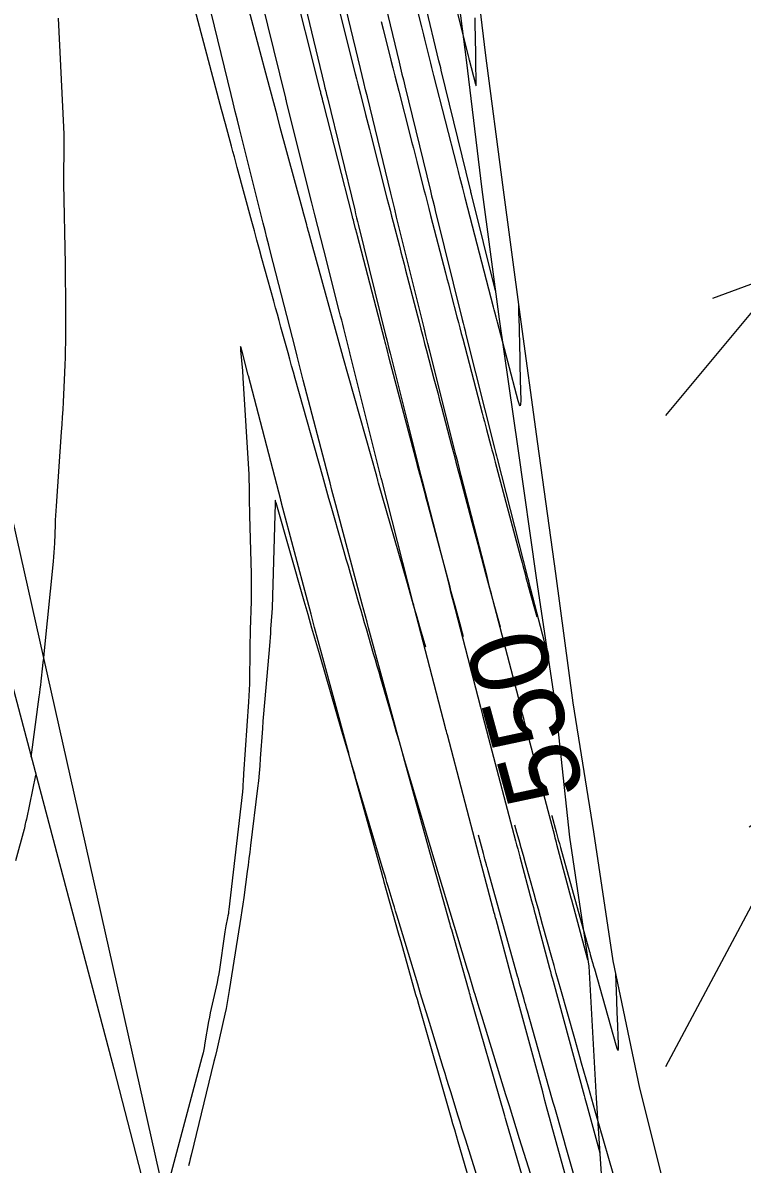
# Model space of a CAD drawing. Extents: x 954385 to 988206, y 1868364 to 1924553.
# Drawn here: x 957857.8 to 957913, y 1919611.4 to 1919699.1 of the extents above; entities that cross this region are included whole.
import ezdxf

# ---------------------------------------------------------------- set-up
doc = ezdxf.new("R2010")
doc.units = 0
for name, color, linetype in [('1', 7, 'Continuous'), ('Default', 7, 'Continuous'), ('Ex_Contour Labels', 7, 'Continuous'), ('Ex_Major Contours', 7, 'Continuous'), ('Ex_Minor Contours', 7, 'Continuous'), ('Perimeter', 7, 'Continuous'), ('Slopes', 7, 'Continuous')]:
    doc.layers.add(name, color=color, linetype=linetype)

msp = doc.modelspace()

# ---------------------------------------------------------------- linework, layer by layer
msp.add_lwpolyline([(957857.224, 1919634.741), (957857.897, 1919637.166), (957857.914, 1919637.23), (957857.93, 1919637.294), (957857.945, 1919637.359), (957857.96, 1919637.424), (957858.037, 1919637.793), (957858.04, 1919637.803), (957858.042, 1919637.814), (957858.045, 1919637.824), (957858.047, 1919637.834), (957858.059, 1919637.875), (957858.061, 1919637.886), (957858.064, 1919637.896), (957858.067, 1919637.906), (957858.069, 1919637.917), (957858.774, 1919641.289)])
at = {"layer": '1'}
for points in [[(957890.519, 1919706.211), (957891.799, 1919696.25), (957893.016, 1919686.274), (957894.336, 1919676.322), (957895.78, 1919666.397), (957897.186, 1919656.464), (957898.672, 1919646.548), (957899.744, 1919636.541), (957900.425, 1919631.907), (957901.213, 1919626.621), (957901.79, 1919616.502), (957902.451, 1919606.402), (957903.226, 1919596.327), (957904.28, 1919586.315), (957905.605, 1919576.364), (957907.064, 1919566.442), (957908.777, 1919559.571)], [(957894.046, 1919678.504), (957892.213, 1919685.917), (957892.192, 1919686.001), (957892.171, 1919686.085), (957892.151, 1919686.169), (957892.13, 1919686.253), (957889.894, 1919695.436), (957889.849, 1919695.619), (957889.805, 1919695.802), (957889.761, 1919695.985), (957889.717, 1919696.169), (957887.599, 1919705.006)], [(957878.8, 1919703.107), (957880.899, 1919694.347), (957880.961, 1919694.089), (957881.023, 1919693.832), (957881.086, 1919693.574), (957881.148, 1919693.316), (957883.245, 1919684.709), (957883.317, 1919684.411), (957883.39, 1919684.114), (957883.463, 1919683.817), (957883.536, 1919683.52), (957885.622, 1919675.092), (957885.707, 1919674.748), (957885.792, 1919674.404), (957885.878, 1919674.061), (957885.964, 1919673.718), (957888.027, 1919665.509), (957888.129, 1919665.106), (957888.231, 1919664.703), (957888.333, 1919664.3), (957888.436, 1919663.897), (957890.462, 1919655.959), (957890.583, 1919655.484), (957890.705, 1919655.009), (957890.827, 1919654.535), (957890.95, 1919654.061), (957892.906, 1919646.512), (957893.06, 1919645.918), (957893.215, 1919645.324), (957893.37, 1919644.731), (957893.526, 1919644.137), (957895.597, 1919636.265), (957895.679, 1919635.956), (957895.76, 1919635.647), (957895.842, 1919635.337), (957895.925, 1919635.028), (957896.825, 1919631.641), (957896.893, 1919631.385), (957896.962, 1919631.13), (957897.03, 1919630.875), (957897.098, 1919630.619), (957898.205, 1919626.488), (957898.274, 1919626.233), (957898.342, 1919625.977), (957898.411, 1919625.722), (957898.48, 1919625.467), (957900.859, 1919616.686), (957900.91, 1919616.501), (957900.96, 1919616.316), (957901.011, 1919616.131), (957901.061, 1919615.946), (957902.065, 1919612.295)], [(957901.139, 1919627.121), (957899.91, 1919631.708), (957899.889, 1919631.787), (957899.867, 1919631.866), (957898.774, 1919635.976), (957898.731, 1919636.14), (957898.688, 1919636.303), (957898.644, 1919636.467), (957898.601, 1919636.63), (957896.321, 1919645.299), (957896.231, 1919645.64), (957896.142, 1919645.981), (957896.053, 1919646.322), (957895.964, 1919646.664), (957893.861, 1919654.78), (957893.746, 1919655.223), (957893.632, 1919655.666), (957893.518, 1919656.11), (957893.405, 1919656.553), (957891.429, 1919664.296), (957891.293, 1919664.828), (957891.158, 1919665.36), (957891.024, 1919665.892), (957890.89, 1919666.424), (957889.022, 1919673.857), (957888.87, 1919674.459), (957888.72, 1919675.061), (957888.57, 1919675.664), (957888.421, 1919676.266), (957886.619, 1919683.549), (957886.468, 1919684.16), (957886.318, 1919684.771), (957886.168, 1919685.382), (957886.019, 1919685.994), (957884.217, 1919693.391), (957884.084, 1919693.94), (957883.951, 1919694.489), (957883.819, 1919695.038), (957883.687, 1919695.587), (957881.857, 1919703.225)], [(957884.792, 1919703.846), (957886.661, 1919696.05), (957886.769, 1919695.598), (957886.878, 1919695.145), (957886.988, 1919694.693), (957887.097, 1919694.241), (957889.061, 1919686.178), (957889.153, 1919685.803), (957889.244, 1919685.428), (957889.337, 1919685.053), (957889.429, 1919684.678), (957891.503, 1919676.295), (957891.575, 1919676.007), (957891.647, 1919675.718), (957891.719, 1919675.43), (957891.791, 1919675.141), (957893.986, 1919666.407), (957894.035, 1919666.212), (957894.085, 1919666.017), (957894.134, 1919665.821), (957894.184, 1919665.626), (957896.518, 1919656.48), (957896.539, 1919656.401), (957896.559, 1919656.323), (957896.579, 1919656.245), (957896.599, 1919656.167), (957898.096, 1919650.39)], [(957900.382, 1919607.112), (957898.392, 1919614.352), (957898.212, 1919615.006), (957898.034, 1919615.659), (957897.856, 1919616.313), (957897.678, 1919616.967), (957895.615, 1919624.581), (957895.515, 1919624.951), (957895.415, 1919625.32), (957895.316, 1919625.69), (957895.217, 1919626.06), (957894.103, 1919630.216), (957894.069, 1919630.345), (957894.034, 1919630.473), (957894, 1919630.601), (957893.966, 1919630.73), (957892.882, 1919634.803), (957892.858, 1919634.896), (957892.833, 1919634.99), (957892.808, 1919635.083), (957892.784, 1919635.176), (957890.361, 1919644.386), (957890.324, 1919644.526), (957890.287, 1919644.667), (957890.251, 1919644.808), (957890.214, 1919644.948), (957887.818, 1919654.194), (957887.797, 1919654.273), (957887.777, 1919654.352), (957887.757, 1919654.432), (957887.736, 1919654.511), (957885.322, 1919663.97), (957885.312, 1919664.008), (957885.303, 1919664.046), (957885.293, 1919664.084), (957885.284, 1919664.122), (957882.868, 1919673.735), (957882.861, 1919673.76), (957882.402, 1919675.615), (957882.325, 1919675.927), (957882.247, 1919676.238), (957882.169, 1919676.549), (957882.09, 1919676.859), (957880.869, 1919681.643), (957880.64, 1919682.544), (957880.412, 1919683.446), (957880.185, 1919684.347), (957879.959, 1919685.249), (957878.018, 1919693.015), (957878.001, 1919693.082), (957877.984, 1919693.15), (957877.968, 1919693.217), (957877.951, 1919693.284), (957875.656, 1919702.664)], [(957897.591, 1919605.464), (957894.933, 1919614.566), (957894.879, 1919614.753), (957894.825, 1919614.939), (957894.771, 1919615.126), (957894.717, 1919615.313), (957892.147, 1919624.279), (957892.106, 1919624.424), (957892.064, 1919624.568), (957892.023, 1919624.713), (957891.982, 1919624.858), (957890.695, 1919629.411), (957890.654, 1919629.558), (957890.612, 1919629.705), (957890.571, 1919629.852), (957890.53, 1919629.999), (957889.556, 1919633.479), (957889.454, 1919633.844), (957889.352, 1919634.208), (957889.251, 1919634.573), (957889.15, 1919634.938), (957887.1, 1919642.361), (957886.894, 1919643.11), (957886.689, 1919643.859), (957886.484, 1919644.609), (957886.28, 1919645.359), (957884.318, 1919652.605), (957884.194, 1919653.063), (957884.071, 1919653.521), (957883.948, 1919653.979), (957883.826, 1919654.437), (957881.801, 1919662.061), (957881.651, 1919662.627), (957881.502, 1919663.193), (957881.354, 1919663.759), (957881.206, 1919664.326), (957879.301, 1919671.643), (957879.141, 1919672.259), (957878.981, 1919672.876), (957878.823, 1919673.493), (957878.665, 1919674.11), (957876.79, 1919681.457), (957876.649, 1919682.013), (957876.508, 1919682.57), (957876.368, 1919683.126), (957876.228, 1919683.683), (957874.409, 1919690.961), (957874.246, 1919691.618), (957874.083, 1919692.274), (957873.921, 1919692.931), (957873.76, 1919693.588), (957871.959, 1919700.947)], [(957893.365, 1919605.696), (957891.193, 1919613.133), (957891.058, 1919613.598), (957890.923, 1919614.064), (957890.788, 1919614.529), (957890.655, 1919614.995), (957888.372, 1919622.957), (957888.267, 1919623.325), (957888.162, 1919623.693), (957888.057, 1919624.06), (957887.953, 1919624.428), (957886.802, 1919628.501), (957886.756, 1919628.665), (957886.71, 1919628.829), (957886.663, 1919628.994), (957886.617, 1919629.158), (957885.519, 1919633.082), (957885.484, 1919633.207), (957885.449, 1919633.333), (957885.414, 1919633.458), (957885.379, 1919633.584), (957882.882, 1919642.628), (957882.833, 1919642.806), (957882.784, 1919642.983), (957882.736, 1919643.161), (957882.688, 1919643.338), (957880.725, 1919650.584), (957880.447, 1919651.615), (957880.169, 1919652.645), (957879.894, 1919653.676), (957879.619, 1919654.707), (957877.633, 1919662.185), (957877.615, 1919662.251), (957877.598, 1919662.317), (957877.581, 1919662.383), (957877.564, 1919662.449), (957875.083, 1919671.976), (957875.074, 1919672.012), (957875.071, 1919672.023), (957874.58, 1919673.948), (957874.523, 1919674.149), (957874.489, 1919674.214), (957874.479, 1919674.142), (957874.492, 1919673.933), (957874.633, 1919672.366), (957874.637, 1919672.32), (957874.64, 1919672.274), (957874.643, 1919672.228), (957874.645, 1919672.182), (957874.653, 1919671.998), (957874.655, 1919671.952), (957874.657, 1919671.905), (957874.659, 1919671.859), (957874.662, 1919671.813), (957875.107, 1919664.398), (957875.121, 1919664.135), (957875.131, 1919663.872), (957875.138, 1919663.609), (957875.142, 1919663.347), (957875.151, 1919662.295), (957875.154, 1919662.032), (957875.158, 1919661.769), (957875.163, 1919661.506), (957875.169, 1919661.243), (957875.291, 1919656.772), (957875.301, 1919656.248), (957875.305, 1919655.724), (957875.3, 1919655.2), (957875.289, 1919654.675), (957875.225, 1919652.451), (957875.213, 1919651.99), (957875.203, 1919651.53), (957875.195, 1919651.069), (957875.19, 1919650.608), (957875.174, 1919648.765), (957875.166, 1919648.304), (957875.152, 1919647.844), (957875.13, 1919647.384), (957875.101, 1919646.924), (957874.717, 1919641.399), (957874.709, 1919641.284), (957874.702, 1919641.169), (957874.696, 1919641.054), (957874.69, 1919640.939), (957874.667, 1919640.478), (957874.661, 1919640.363), (957874.652, 1919640.248), (957874.642, 1919640.133), (957874.63, 1919640.019), (957873.591, 1919630.98), (957873.571, 1919630.822), (957873.547, 1919630.664), (957873.52, 1919630.508), (957873.49, 1919630.351), (957873.362, 1919629.727), (957873.331, 1919629.571), (957873.303, 1919629.414), (957873.276, 1919629.257), (957873.252, 1919629.1), (957872.856, 1919626.369), (957872.804, 1919626.034), (957872.745, 1919625.701), (957872.679, 1919625.369), (957872.606, 1919625.039), (957872.301, 1919623.719), (957872.227, 1919623.388), (957872.158, 1919623.057), (957872.093, 1919622.724), (957872.034, 1919622.391), (957871.751, 1919620.75), (957871.68, 1919620.366), (957871.601, 1919619.984), (957871.513, 1919619.604), (957871.417, 1919619.226), (957868.747, 1919609.237)]]:
    msp.add_lwpolyline(points, dxfattribs=at)
at = {"layer": 'Default'}
msp.add_line((958200.602, 1918129.717), (957843.865, 1919719.405), dxfattribs=at)
at = {"layer": 'Ex_Major Contours'}
for points in [[(957881.873, 1919700.777), (957883.286, 1919695.163), (957883.384, 1919694.773), (957883.483, 1919694.384), (957883.582, 1919693.994), (957883.681, 1919693.604), (957884.079, 1919692.046), (957884.179, 1919691.656), (957884.278, 1919691.266), (957884.378, 1919690.877), (957884.478, 1919690.487), (957885.725, 1919685.611), (957885.843, 1919685.151), (957885.961, 1919684.691), (957886.08, 1919684.23), (957886.199, 1919683.77), (957886.676, 1919681.93), (957886.795, 1919681.47), (957886.915, 1919681.01), (957887.034, 1919680.549), (957887.153, 1919680.089), (957888.19, 1919676.095), (957888.331, 1919675.551), (957888.473, 1919675.006), (957888.616, 1919674.462), (957888.759, 1919673.918), (957889.332, 1919671.742), (957889.475, 1919671.197), (957889.618, 1919670.653), (957889.762, 1919670.109), (957889.905, 1919669.565), (957890.681, 1919666.617), (957890.851, 1919665.973), (957891.021, 1919665.329), (957891.192, 1919664.685), (957891.364, 1919664.041), (957892.094, 1919661.309), (957892.245, 1919660.744), (957892.396, 1919660.179), (957892.547, 1919659.614), (957892.698, 1919659.049), (957893.301, 1919656.79), (957893.453, 1919656.225), (957893.604, 1919655.66), (957893.757, 1919655.096), (957893.909, 1919654.531), (957894.409, 1919652.689)], [(957898.361, 1919638.219), (957898.374, 1919638.174), (957898.708, 1919636.955), (957898.792, 1919636.65), (957898.877, 1919636.346), (957898.961, 1919636.041), (957899.046, 1919635.737), (957901.18, 1919628.087), (957901.219, 1919627.949), (957901.257, 1919627.81), (957901.296, 1919627.671), (957901.335, 1919627.533), (957901.489, 1919626.978), (957901.528, 1919626.839), (957901.567, 1919626.701), (957901.606, 1919626.562), (957901.645, 1919626.424), (957903.297, 1919620.588), (957903.403, 1919620.263), (957903.473, 1919620.16), (957903.508, 1919620.279), (957903.507, 1919620.622), (957903.422, 1919622.671), (957903.409, 1919623.007), (957903.395, 1919623.344), (957903.381, 1919623.68), (957903.367, 1919624.017), (957903.283, 1919626.035)]]:
    msp.add_lwpolyline(points, dxfattribs=at)
at = {"layer": 'Ex_Minor Contours'}
for points in [[(957889.645, 1919705.739), (957891.955, 1919696.556), (957892.007, 1919696.351), (957892.02, 1919696.3), (957892.033, 1919696.248), (957892.512, 1919694.372), (957892.54, 1919694.277), (957892.56, 1919694.247), (957892.57, 1919694.281), (957892.573, 1919694.38), (957892.564, 1919694.903), (957892.56, 1919695.164), (957892.555, 1919695.425), (957892.544, 1919696.103), (957892.542, 1919696.259), (957892.539, 1919696.416), (957892.537, 1919696.572), (957892.535, 1919696.729), (957892.505, 1919699.039), (957892.5, 1919699.476)], [(957895.82, 1919677.378), (957895.826, 1919677.042), (957895.832, 1919676.754), (957895.833, 1919676.706), (957895.834, 1919676.658), (957895.835, 1919676.61), (957895.836, 1919676.562), (957895.914, 1919673.264), (957895.924, 1919672.865), (957895.933, 1919672.465), (957895.943, 1919672.065), (957895.952, 1919671.665), (957895.99, 1919670.066), (957895.985, 1919669.765), (957895.953, 1919669.66), (957895.893, 1919669.752), (957895.805, 1919670.04), (957894.211, 1919676.093), (957894.186, 1919676.188), (957894.161, 1919676.283), (957894.137, 1919676.378), (957894.112, 1919676.473), (957894.013, 1919676.853), (957893.964, 1919677.043), (957893.915, 1919677.233), (957891.759, 1919685.546), (957891.705, 1919685.757), (957891.65, 1919685.968), (957891.596, 1919686.178), (957891.542, 1919686.389), (957891.326, 1919687.232), (957891.273, 1919687.443), (957891.219, 1919687.654), (957891.165, 1919687.865), (957891.111, 1919688.076), (957889.333, 1919695.039), (957889.254, 1919695.35), (957889.175, 1919695.661), (957889.096, 1919695.972), (957889.017, 1919696.283), (957888.704, 1919697.527), (957888.626, 1919697.838), (957888.548, 1919698.149), (957888.469, 1919698.46), (957888.391, 1919698.772), (957886.933, 1919704.566)], [(957891.599, 1919651.922), (957891.525, 1919652.196), (957891.334, 1919652.902), (957890.951, 1919654.315), (957890.855, 1919654.668), (957890.76, 1919655.022), (957890.665, 1919655.375), (957890.57, 1919655.729), (957888.882, 1919662.044), (957888.812, 1919662.309), (957888.741, 1919662.574), (957888.67, 1919662.838), (957888.6, 1919663.103), (957888.317, 1919664.161), (957888.246, 1919664.426), (957888.176, 1919664.691), (957888.106, 1919664.955), (957888.036, 1919665.22), (957886.133, 1919672.449), (957886.032, 1919672.832), (957885.931, 1919673.216), (957885.729, 1919673.984), (957885.679, 1919674.176), (957885.628, 1919674.368), (957885.578, 1919674.56), (957885.528, 1919674.752), (957883.459, 1919682.728), (957883.424, 1919682.86), (957883.39, 1919682.993), (957883.356, 1919683.125), (957883.321, 1919683.258), (957883.184, 1919683.787), (957883.15, 1919683.92), (957883.116, 1919684.052), (957883.082, 1919684.184), (957883.048, 1919684.317), (957880.851, 1919692.904), (957880.808, 1919693.072), (957880.765, 1919693.24), (957880.68, 1919693.577), (957880.658, 1919693.661), (957880.637, 1919693.745), (957880.615, 1919693.829), (957880.594, 1919693.913), (957878.309, 1919702.992)], [(957888.71, 1919651.132), (957888.307, 1919652.513), (957888.04, 1919653.432), (957887.773, 1919654.351), (957887.508, 1919655.271), (957887.244, 1919656.191), (957885.086, 1919663.721), (957885.027, 1919663.929), (957885.012, 1919663.981), (957884.997, 1919664.033), (957884.935, 1919664.252), (957882.344, 1919673.474), (957882.323, 1919673.548), (957882.303, 1919673.621), (957882.282, 1919673.695), (957882.262, 1919673.768), (957880.034, 1919681.844), (957879.877, 1919682.416), (957879.719, 1919682.987), (957879.68, 1919683.129), (957879.641, 1919683.272), (957879.602, 1919683.415), (957879.563, 1919683.558), (957879.337, 1919684.394), (957879.207, 1919684.875), (957877.537, 1919691.046), (957877.282, 1919691.99), (957877.028, 1919692.935), (957876.775, 1919693.88), (957876.524, 1919694.826), (957874.597, 1919702.08)], [(957897.271, 1919609.015), (957895.907, 1919613.375), (957895.643, 1919614.219), (957895.38, 1919615.064), (957895.119, 1919615.909), (957894.858, 1919616.754), (957893.002, 1919622.793), (957892.831, 1919623.35), (957892.545, 1919624.279), (957892.488, 1919624.465), (957892.431, 1919624.65), (957892.375, 1919624.836), (957892.318, 1919625.022), (957892.024, 1919625.997), (957891.888, 1919626.446), (957891.752, 1919626.895), (957889.734, 1919633.562), (957889.631, 1919633.905), (957889.528, 1919634.248), (957889.425, 1919634.591), (957889.323, 1919634.934), (957888.915, 1919636.307), (957888.813, 1919636.651), (957888.712, 1919636.994), (957888.61, 1919637.337), (957888.508, 1919637.68), (957887.106, 1919642.402), (957886.891, 1919643.129), (957886.676, 1919643.856), (957886.462, 1919644.584), (957886.249, 1919645.312), (957885.251, 1919648.733), (957885.113, 1919649.207), (957884.974, 1919649.681), (957884.836, 1919650.156), (957884.698, 1919650.63), (957884.144, 1919652.527), (957884.006, 1919653.001), (957883.869, 1919653.475), (957883.732, 1919653.95), (957883.595, 1919654.425), (957882.918, 1919656.79), (957882.76, 1919657.342), (957882.601, 1919657.895), (957882.443, 1919658.447), (957882.285, 1919659), (957881.433, 1919661.973), (957881.271, 1919662.539), (957881.11, 1919663.105), (957880.95, 1919663.671), (957880.79, 1919664.238), (957878.677, 1919671.757), (957878.539, 1919672.251), (957878.401, 1919672.745), (957878.263, 1919673.24), (957878.127, 1919673.735), (957877.581, 1919675.714), (957877.444, 1919676.209), (957877.308, 1919676.704), (957877.171, 1919677.199), (957877.035, 1919677.693), (957876.13, 1919680.974), (957875.934, 1919681.685), (957875.739, 1919682.397), (957875.545, 1919683.109), (957875.352, 1919683.822), (957874.229, 1919687.971), (957874.118, 1919688.38), (957874.008, 1919688.788), (957873.897, 1919689.197), (957873.787, 1919689.606), (957873.322, 1919691.322), (957873.223, 1919691.69), (957873.124, 1919692.059), (957873.025, 1919692.428), (957872.927, 1919692.797), (957871, 1919700.051)], [(957858.407, 1919642.672), (957859.031, 1919647.329), (957859.069, 1919647.625), (957859.106, 1919647.92), (957859.142, 1919648.216), (957859.176, 1919648.511), (957859.309, 1919649.695), (957859.342, 1919649.991), (957859.374, 1919650.287), (957859.405, 1919650.583), (957859.435, 1919650.879), (957860.116, 1919657.703), (957860.149, 1919658.057), (957860.176, 1919658.41), (957860.197, 1919658.765), (957860.213, 1919659.119), (957860.266, 1919660.538), (957860.281, 1919660.893), (957860.299, 1919661.247), (957860.319, 1919661.602), (957860.343, 1919661.956), (957860.749, 1919667.66), (957860.788, 1919668.231), (957860.824, 1919668.803), (957860.857, 1919669.375), (957860.887, 1919669.948), (957861.001, 1919672.237), (957861.026, 1919672.81), (957861.044, 1919673.382), (957861.055, 1919673.955), (957861.059, 1919674.528), (957861.063, 1919677.673), (957861.061, 1919678.389), (957861.057, 1919679.104), (957861.049, 1919679.819), (957861.037, 1919680.534), (957860.919, 1919686.745), (957860.915, 1919687.003), (957860.913, 1919687.261), (957860.914, 1919687.519), (957860.917, 1919687.777), (957860.935, 1919688.978), (957860.938, 1919689.151), (957860.939, 1919689.325), (957860.94, 1919689.498), (957860.939, 1919689.672), (957860.937, 1919690.365), (957860.935, 1919690.539), (957860.932, 1919690.712), (957860.926, 1919690.885), (957860.918, 1919691.059), (957860.499, 1919699.45)], [(957885.277, 1919699.197), (957885.427, 1919698.601), (957886.028, 1919696.215), (957886.178, 1919695.619), (957886.329, 1919695.022), (957886.481, 1919694.426), (957886.633, 1919693.83), (957887.485, 1919690.493), (957887.617, 1919689.977), (957887.749, 1919689.46), (957887.881, 1919688.944), (957888.013, 1919688.427), (957888.541, 1919686.362), (957888.673, 1919685.845), (957888.806, 1919685.329), (957888.939, 1919684.813), (957889.073, 1919684.297), (957890.22, 1919679.872), (957890.33, 1919679.449), (957890.439, 1919679.026), (957890.549, 1919678.604), (957890.659, 1919678.181), (957891.097, 1919676.49), (957891.207, 1919676.067), (957891.318, 1919675.645), (957891.428, 1919675.222), (957891.539, 1919674.8), (957893.039, 1919669.101), (957893.122, 1919668.788), (957893.204, 1919668.474), (957893.287, 1919668.161), (957893.369, 1919667.848), (957893.699, 1919666.594), (957893.782, 1919666.28), (957893.865, 1919665.967), (957893.948, 1919665.654), (957894.032, 1919665.341), (957895.951, 1919658.156), (957896.001, 1919657.97), (957896.05, 1919657.784), (957896.1, 1919657.599), (957896.15, 1919657.413), (957896.348, 1919656.67), (957896.398, 1919656.484), (957896.448, 1919656.298), (957896.498, 1919656.113), (957896.548, 1919655.927), (957897.218, 1919653.456)], [(957894.155, 1919605.624), (957891.767, 1919613.256), (957891.621, 1919613.721), (957891.476, 1919614.187), (957891.332, 1919614.654), (957891.188, 1919615.12), (957890.615, 1919616.986), (957890.471, 1919617.452), (957890.328, 1919617.919), (957890.185, 1919618.385), (957890.041, 1919618.852), (957888.978, 1919622.311), (957888.753, 1919623.043), (957888.53, 1919623.775), (957888.307, 1919624.508), (957888.084, 1919625.241), (957886.577, 1919630.222), (957886.482, 1919630.537), (957886.387, 1919630.852), (957886.292, 1919631.167), (957886.196, 1919631.482), (957885.815, 1919632.742), (957885.72, 1919633.057), (957885.625, 1919633.372), (957885.531, 1919633.687), (957885.437, 1919634.003), (957883.369, 1919640.965), (957883.25, 1919641.368), (957883.13, 1919641.771), (957882.873, 1919642.638), (957882.822, 1919642.809), (957882.772, 1919642.98), (957882.721, 1919643.151), (957882.671, 1919643.322), (957882.422, 1919644.177), (957882.272, 1919644.69), (957880.566, 1919650.537), (957880.266, 1919651.568), (957879.967, 1919652.6), (957879.669, 1919653.632), (957879.373, 1919654.665), (957877.209, 1919662.217), (957877.201, 1919662.246), (957877.159, 1919662.395), (957877.153, 1919662.414), (957877.148, 1919662.42), (957877.145, 1919662.413), (957877.144, 1919662.393), (957877.143, 1919662.272), (957877.143, 1919662.244), (957877.143, 1919662.215), (957877.142, 1919662.186), (957877.141, 1919662.157), (957876.943, 1919655.078), (957876.933, 1919654.758), (957876.919, 1919654.438), (957876.902, 1919654.117), (957876.882, 1919653.798), (957876.795, 1919652.518), (957876.773, 1919652.198), (957876.748, 1919651.879), (957876.723, 1919651.559), (957876.695, 1919651.24), (957876.338, 1919647.165), (957876.289, 1919646.594), (957876.243, 1919646.022), (957876.199, 1919645.45), (957876.158, 1919644.877), (957876, 1919642.588), (957875.957, 1919642.016), (957875.906, 1919641.445), (957875.849, 1919640.874), (957875.784, 1919640.304), (957875.251, 1919635.887), (957875.189, 1919635.387), (957875.126, 1919634.888), (957875.061, 1919634.388), (957874.995, 1919633.889), (957874.725, 1919631.893), (957874.656, 1919631.394), (957874.584, 1919630.896), (957874.51, 1919630.398), (957874.432, 1919629.901), (957873.618, 1919624.76), (957873.542, 1919624.302), (957873.459, 1919623.845), (957873.369, 1919623.39), (957873.271, 1919622.935), (957872.867, 1919621.122), (957872.764, 1919620.669), (957872.66, 1919620.216), (957872.553, 1919619.764), (957872.444, 1919619.313), (957870.685, 1919612.107), (957870.62, 1919611.836), (957870.557, 1919611.565), (957870.496, 1919611.293)], [(957903.419, 1919609.554), (957901.711, 1919615.503), (957901.579, 1919615.964), (957901.447, 1919616.425), (957901.316, 1919616.887), (957901.185, 1919617.348), (957900.664, 1919619.193), (957900.533, 1919619.655), (957900.403, 1919620.116), (957900.272, 1919620.577), (957900.142, 1919621.039), (957899.069, 1919624.83), (957898.895, 1919625.446), (957898.721, 1919626.062), (957898.548, 1919626.679), (957898.376, 1919627.295), (957897.674, 1919629.818), (957897.51, 1919630.407), (957897.345, 1919630.996), (957897.181, 1919631.585), (957897.017, 1919632.174), (957896.36, 1919634.529), (957896.196, 1919635.118), (957896.032, 1919635.708), (957895.869, 1919636.297), (957895.707, 1919636.886), (957895.552, 1919637.452)], [(957901.052, 1919607.229), (957899.646, 1919612.134), (957899.542, 1919612.499), (957899.437, 1919612.864), (957899.332, 1919613.23), (957899.227, 1919613.595), (957898.808, 1919615.056), (957898.703, 1919615.421), (957898.599, 1919615.786), (957898.495, 1919616.152), (957898.392, 1919616.517), (957896.51, 1919623.174), (957896.446, 1919623.399), (957896.383, 1919623.624), (957896.319, 1919623.849), (957896.255, 1919624.074), (957896.001, 1919624.973), (957895.937, 1919625.198), (957895.874, 1919625.423), (957895.811, 1919625.648), (957895.748, 1919625.874), (957893.495, 1919633.96), (957893.464, 1919634.071), (957893.434, 1919634.182), (957893.403, 1919634.293), (957893.372, 1919634.404), (957893.248, 1919634.847), (957893.217, 1919634.958), (957893.186, 1919635.069), (957893.156, 1919635.18), (957893.125, 1919635.291), (957892.742, 1919636.684)]]:
    msp.add_lwpolyline(points, dxfattribs=at)
at = {"layer": 'Perimeter'}
for points in [[(957817.372, 1919769.232), (957831.573, 1919731.267), (957843.682, 1919693.162), (957854.383, 1919657.846), (957864.753, 1919618.743), (957875.296, 1919577.825), (957884.584, 1919537.635), (957892.533, 1919502.268), (957902.065, 1919460.502), (957910.491, 1919421.742), (957920.001, 1919379.492)], [(957892.09, 1919706.564), (957893.285, 1919696.583), (957894.589, 1919686.627), (957895.913, 1919676.676), (957897.289, 1919666.736), (957898.653, 1919656.793), (957899.988, 1919646.844), (957901.581, 1919636.953), (957903.073, 1919627.039), (957905.12, 1919617.249), (957907.548, 1919607.546), (957910.107, 1919597.871), (957911.76, 1919591.16), (957912.581, 1919588.178), (957915.105, 1919578.495)]]:
    msp.add_lwpolyline(points, dxfattribs=at)
at = {"layer": 'Slopes'}
for points in [[(957907.131, 1919668.928), (957916.355, 1919679.981), (957915.329, 1919674.069), (957916.355, 1919679.981), (957910.722, 1919677.913)], [(957907.131, 1919618.928), (957918.618, 1919640.482), (957918.822, 1919634.486), (957918.618, 1919640.482), (957913.527, 1919637.308)]]:
    msp.add_lwpolyline(points, dxfattribs=at)

# ---------------------------------------------------------------- texts
at = {"layer": 'Ex_Contour Labels'}
msp.add_text('550', height=6, rotation=105.27818, dxfattribs=at).set_placement((957900.973, 1919640.043))

doc.saveas('drawing.dxf')
